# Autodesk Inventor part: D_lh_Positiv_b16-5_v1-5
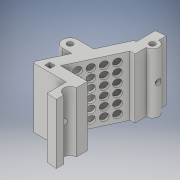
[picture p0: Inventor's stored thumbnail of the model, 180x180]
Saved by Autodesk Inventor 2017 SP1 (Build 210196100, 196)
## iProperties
Part Number: D_lh_Positiv_b16-5_v1-5
Material: Generisch
Document SubType Name: Modeling
Designer: haesner
Density: 1 g/cm^3
Appearance: Vorgabe
Part Number: D_lh_Positiv_b16-5_v1-6_3D-Druck
Author: haesner
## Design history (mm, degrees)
sketch "Skizze1"
  geometry: L1 (0, 9.5)-(-2, 9.5); L2 (-2, 9.5)-(-10.86, -9.5); L3 (-10.86, -9.5)-(0, -9.5); L4 (0, 22)-(0, 19); L5 (0, 14)-(0, 9.5); L6 (0, -22)-(0, -19); L7 (0, -9.5)-(0, -14); L8 (-26.9, 0)-(7.4, 0) reference; L9 (0, -30.8)-(0, 30.8) reference; C1 r 1.15 at (-16.5, 0); C2 r 1.15 at (0, 16.5); A1 r 22 centre (0, 0) between (0, 22) and (0, -22); A2 r 2.5 centre (0, 16.5) between (0, 14) and (0, 19); A3 r 2.5 centre (0, -16.5) between (0, -14) and (0, -19); 1 further point
  constraints: 14 end point, 6 point on circle, 5 centre point, 4 collinear, 4 point on line, 2 coincident, 2 equal radius, 1 horizontal, 1 parallel, 1 other
  dimensions: "d1" = 22 radius of A1; "d4" = 2.3 diameter of C2; "d5" = 2.5 radius of A3; "d6" = 16.5 distance from line of L8 A3.centre; "d7" = 16.5 distance from line of L8 A2.centre (= d6); "d8" = 16.5 distance from line of L9 C1.centre (= d6); "d10" = 19 distance between parallel lines of L3 L1; "d172" = 2 distance of L1.start L1.end; "d173" = 25 deg angle of L9 L2
extrude "Extrusion1" new body sketch "Skizze1" distance "d11" = 3; taper "d12" = 0 deg
sketch "Skizze12"
  geometry: L1 (0, 19)-(0, 22); L2 (0, -14)-(0, -9.5) reference; L3 (0, -9.5)-(-10.86, -9.5) reference; L4 (-10.86, -9.5)-(-2, 9.5) reference; L5 (-2, 9.5)-(0, 9.5) reference; L6 (0, 9.5)-(0, 14) reference; L7 (-4.867, 14)-(-17.569, -13.241); L8 (0, -22)-(0, -19) reference; L9 (-16.971, -14)-(-4, -14); L10 (-4, -14)-(-4, -21.633); L11 (-16.5, -3)-(-12.794, -3); L12 (-16.5, 3)-(-9.996, 3); L13 (-26.9, 0)-(7.4, 0) reference; L14 (-4, 21.633)-(-4, 14); L15 (-4.867, 14)-(-4, 14); C1 r 1.15 at (0, 16.5); C2 r 1.15 at (0, 16.5); C3 r 1.15 at (-16.5, 0) reference; A1 r 2.5 centre (0, 16.5) between (0, 14) and (0, 19); A2 r 22 centre (0, 0) between (-4, -21.633) and (0, -22); A3 r 2.5 centre (0, -16.5) between (0, -14) and (0, -19) reference; A4 r 22 centre (0, 0) between (0, 22) and (0, -22) reference; A5 r 3 centre (-16.5, 0) between (-16.5, 3) and (-16.5, -3); A6 r 22 centre (0, 0) between (0, 22) and (-4, 21.633); A7 r 22 centre (0, 0) between (-17.569, -13.241) and (-16.971, -14); 2 further points
  constraints: 16 end point, 11 point on circle, 7 centre point, 5 coincident, 4 horizontal, 2 point on line, 2 vertical, 1 parallel, 1 other
  dimensions: "d143" = 4.5 distance between parallel lines of L4 L7 (derived); "d145" = 4 distance between parallel lines of L8 L10 (derived); "d168" = 3 radius of A5; "d169" = 6 distance between parallel lines of L11 L12; "d174" = 4 distance between parallel lines of L1 L14 (derived); "d175" = 4.5 distance between parallel lines of L15 L5 (derived); "d176" = 4.5 distance between parallel lines of L3 L9 (derived)
extrude "Extrusion11" join sketch "Skizze12" distance "d109" = 18; taper "d110" = 0 deg
sketch "Skizze14"
  geometry: L1 (0, -22)-(0, -19); L2 (0, -14)-(0, -9.5); L3 (0, -9.5)-(-10.86, -9.5); L4 (-10.86, -9.5)-(-2, 9.5); L5 (-2, 9.5)-(0, 9.5); L6 (0, 9.5)-(0, 14); L7 (0, 19)-(0, 22); C1 r 1.15 at (0, 16.5); C2 r 1.15 at (-16.5, 0); A1 r 22 centre (0, 0) between (-4, -21.633) and (0, -22); A2 r 2.5 centre (0, -16.5) between (0, -14) and (0, -19); A3 r 2.5 centre (0, 16.5) between (0, 14) and (0, 19); A4 r 22 centre (0, 0) between (-4, 21.633) and (-17.569, -13.241) reference; A5 r 22 centre (0, 0) between (0, 22) and (-4, 21.633) reference; A6 r 22 centre (0, 0) between (-17.569, -13.241) and (-16.971, -14) reference; A7 r 22 centre (0, 0) between (-16.971, -14) and (-4, -21.633) reference; 1 further point
  constraints: 14 end point, 6 point on circle, 5 centre point
extrude "Extrusion14" join sketch "Skizze14" distance "d151" = 3; taper "d152" = 0 deg
sketch "Skizze7"
  geometry: L1 (6.6, -3.765)-(6.6, -7.765); L2 (6.6, -7.765)-(10.2, -7.765); L3 (10.2, -7.765)-(10.2, -3.765); L4 (10.2, -3.765)-(13.8, -3.765); L5 (13.8, -3.765)-(13.8, -7.765); L6 (13.8, -7.765)-(17.4, -7.765); L7 (17.4, -7.765)-(17.4, -3.765); L8 (17.4, -3.765)-(21, -3.765); L9 (21, -3.765)-(21, -7.765); L10 (21, -7.765)-(21, -11.765); L11 (21, -11.765)-(21, -15.765); L12 (21, -15.765)-(17.4, -15.765); L13 (17.4, -15.765)-(17.4, -11.765); L14 (17.4, -11.765)-(13.8, -11.765); L15 (13.8, -11.765)-(13.8, -15.765); L16 (10.2, -15.765)-(10.2, -11.765); L17 (6.6, -11.765)-(6.6, -15.765); L18 (10.2, -15.765)-(13.8, -15.765); L19 (10.2, -11.765)-(6.6, -11.765); L20 (6.6, -3.765)-(3, -3.765); L21 (3, -3.765)-(3, -7.765); L22 (6.6, -15.765)-(3, -15.765); L23 (3, -15.765)-(3, -11.765); L24 (24, -47.047)-(24, 23.277) reference; L25 (28.8, -7.765)-(-4.8, -7.765) reference
  constraints: 46 end point, 20 point on line, 10 equal length, 10 perpendicular, 3 horizontal, 2 vertical, 1 collinear
  dimensions: "d49" = 4 distance between parallel lines of L6 L14; "d50" = 4 distance of L17.start L17.end; "d59" = 3.6 distance of L7.end L8.end; "d177" = 3 distance between parallel lines of L24 L9
hole "Bohrung1" sketch "Skizze7" diameter "d52" = 3; stored, may be unused: countersink angle "d56" = 90 deg, drill point angle "d58" = 118 deg; dims "d53" = 6, "d54" = 4, "d55" = 2, "d57" = 1.8
sketch "Skizze8"
  geometry: L1 (7.86, -17.4)-(3.86, -17.4); L2 (3.86, -17.4)-(3.86, -13.8); L3 (3.86, -13.8)-(7.86, -13.8); L4 (7.86, -13.8)-(7.86, -10.2); L5 (7.86, -10.2)-(3.86, -10.2); L6 (3.86, -10.2)-(3.86, -6.6); L7 (3.86, -6.6)-(7.86, -6.6); L8 (7.86, -6.6)-(7.86, -3); L9 (7.86, -3)-(3.86, -3); L10 (7.86, -17.4)-(7.86, -21); L11 (7.86, -21)-(3.86, -21); L12 (-16.04, 0)-(18.26, 0) reference; L13 (10.86, 4.8)-(10.86, -28.8) reference; 3 further points; 1 other entity
  constraints: 22 end point, 9 equal length, 4 perpendicular, 3 parallel, 2 horizontal, 2 vertical, 3 other
  dimensions: "d60" = 4 distance of L1.start L1.end; "d61" = 3.6 distance of L1.end L2.end; "d139" = 2.5 dimension on L4; "d178" = 3 distance between parallel lines of L12 L9; "d179" = 3 distance between parallel lines of L13 L4
hole "Bohrung2" sketch "Skizze8" diameter "d64" = 3; stored, may be unused: countersink angle "d68" = 90 deg, drill point angle "d70" = 118 deg; dims "d65" = 6, "d66" = 4, "d67" = 2, "d69" = 1.8
sketch "Skizze6"
  geometry: L1 (10.86, -12.5)-(1, -12.5); L2 (14.17, -9.5)-(3.911, 12.5); L3 (3.911, 12.5)-(1, 12.5); L4 (1, -12.5)-(1, -10.5); L5 (0, -30.8)-(0, 30.8) reference; L6 (11.963, -9.5)-(2.637, 10.5); L7 (10.86, -10.5)-(1, -10.5); L8 (0, -9.5)-(10.86, -9.5) reference; L9 (2.637, 10.5)-(1, 10.5); L10 (1, 10.5)-(1, 12.5); L11 (2, 9.5)-(0, 9.5) reference; L12 (10.86, -9.5)-(2, 9.5) reference; L13 (10.86, -12.5)-(10.86, -10.5); L14 (11.963, -9.5)-(14.17, -9.5); 1 further point
  constraints: 20 end point, 5 horizontal, 2 point on line, 2 vertical, 1 perpendicular
  dimensions: "d41" = 1 distance between parallel lines of L5 L4; "d129" = 2 distance between parallel lines of L2 L6; "d130" = 1 distance between parallel lines of L8 L7; "d131" = 1 distance between parallel lines of L5 L10 (derived); "d132" = 2 distance between parallel lines of L3 L9; "d133" = 2 distance between parallel lines of L7 L1; "d134" = 1 distance between parallel lines of L11 L9 (derived); "d135" = 1 distance between parallel lines of L12 L6 (derived)
extrude "Extrusion6" cut sketch "Skizze6" distance "d39" = 23; taper "d40" = 0 deg
sketch "Skizze16"
  geometry: L1 (9, 38.133)-(9, 5.133); L2 (-7.8, 21.633)-(25.8, 21.633) reference; L3 (-3, -45.327)-(-3, 58.46) reference; 1 further point
  constraints: 2 end point, 1 symmetric about line, 1 vertical
  dimensions: "d160" = 33 distance of L1.start L1.end; "d180" = 12 distance between parallel lines of L3 L1
hole "Bohrung4" sketch "Skizze16" at (9, 38.133), (9, 5.133) diameter "d161" = 2.3; stored, may be unused: countersink angle "d165" = 90 deg, drill point angle "d167" = 118 deg; dims "d162" = 6, "d163" = 4, "d164" = 2, "d166" = 8
sketch "Skizze17"
  geometry: L1 (-4, 21.633)-(-4, 14) reference; L2 (-4, 14)-(-4.867, 14) reference; L3 (-4.867, 14)-(-9.996, 3) reference; L4 (-9.996, 3)-(-16.5, 3) reference; L5 (-16.5, -3)-(-12.794, -3) reference; L6 (-12.794, -3)-(-17.569, -13.241) reference; L7 (-16.971, -14)-(-4, -14) reference; L8 (-4, -14)-(-4, -21.633) reference; A1 r 22 centre (0, 0) between (0, 22) and (0, -22) reference; A2 r 3 centre (-16.5, 0) between (-16.5, 3) and (-16.5, -3) reference; 1 further point
extrude "Extrusion17" cut sketch "Skizze17" distance "d181" = 30; taper "d182" = 0 deg
sketch "Skizze18"
  geometry: L1 (11.963, -12.5)-(14.17, -12.5); L2 (14.17, -12.5)-(14.17, -10.5); L3 (14.17, -10.5)-(11.963, -10.5); L4 (11.963, -10.5)-(11.963, -12.5); L5 (14.17, -9.5)-(11.963, -9.5) reference; L6 (10.86, -10.5)-(10.86, -12.5) reference; 1 further point
  constraints: 8 end point, 4 parallel, 2 point on line, 1 horizontal, 1 perpendicular
extrude "Extrusion18" cut sketch "Skizze18" distance "d183" = 40; taper "d184" = 0 deg
sketch "Skizze19"
  geometry: L1 (11.963, -12.5)-(11.963, -10.5) reference; L2 (10.86, -10.5)-(10.86, -12.5) reference; L3 (14.17, -9.5)-(11.963, -9.5) reference; L4 (11.963, -10.5)-(14.17, -10.5) reference; L5 (10.86, -10.5)-(11.963, -10.5); L6 (10.86, -12.5)-(11.963, -12.5); L7 (11.963, -10.5)-(11.963, -9.5); L8 (14.17, -10.5)-(14.17, -9.5); 1 further point
  constraints: 8 end point, 2 parallel, 1 horizontal, 1 perpendicular
extrude "Extrusion19" cut sketch "Skizze19" distance "d185" = 10; taper "d186" = 0 deg
sketch "Skizze15"
  geometry: L1 (4, 14)-(4, 21.633) reference; L2 (16.971, 14)-(4, 14) reference; L3 (4, -21.633)-(4, -14) reference; L4 (4, -14)-(16.971, -14) reference; L5 (16.5, 3)-(9.996, 3) reference; L6 (12.794, -3)-(16.5, -3) reference; A1 r 22 centre (0, 0) between (0, -22) and (0, 22) reference; A2 r 22 centre (0, 0) between (0, -22) and (0, 22) reference; A3 r 3 centre (16.5, 0) between (16.5, -3) and (16.5, 3) reference; 4 further points; 2 other entities
  constraints: 2 other
extrude "Extrusion16" cut sketch "Skizze15" distance "d170" = 30; taper "d171" = 0 deg
sketch "Skizze13"
  geometry: L1 (9, 38.133)-(9, 5.133); L2 (-7.2, 21.633)-(22.2, 21.633) reference; L3 (-3, -9.167)-(-3, 52.433) reference; 1 further point
  constraints: 2 end point, 1 symmetric about line, 1 vertical
  dimensions: "d114" = 12 distance between parallel lines of L3 L1; "d115" = 33 distance of L1.start L1.end
hole "Bohrung3" sketch "Skizze13" at (9, 38.133), (9, 5.133) diameter "d116" = 2.3; stored, may be unused: countersink angle "d120" = 90 deg, drill point angle "d122" = 118 deg; dims "d117" = 6, "d118" = 4, "d119" = 2, "d121" = 8
sketch "Skizze9"
  geometry: L1 (-4, -20.274)-(-14, -14.5); L2 (-14, -14.5)-(-4, -14.5); L3 (-6.459, 16.5)-(-12.737, 3.038); L4 (-12.737, 3.038)-(-19.081, 5.996); L5 (0, 16.5)-(-33.947, 16.5); L6 (-6.459, 16.5)-(-9.459, 16.5); L7 (-19.081, 5.996)-(-9.459, 16.5); L8 (-4, -14.5)-(-4, -20.274); L9 (-40.966, 0)-(8.169, 0) reference; L10 (0, 25.235)-(0, -27.858) reference; L11 (-1, -12.5)-(-15.569, -12.5) reference; C1 r 1.15 at (0, 16.5) reference; 6 further points; 1 other entity
  constraints: 16 end point, 2 point on line, 1 coincident, 1 horizontal, 1 perpendicular, 1 vertical, 1 other
  dimensions: "d71" = 7 distance of L3.end L4.end; "d72" = 3 distance of L6.end L3.start; "d78" = 30 deg angle of L2 L1; "d100" = 10 distance of L1.end L2.end; "d123" = 4 distance between parallel lines of L10 L8; "d124" = 2 distance between parallel lines of L2 L11; "d125" = 4 dimension on L3
extrude "Extrusion7" cut sketch "Skizze9" distance "d79" = 30; taper "d80" = 0 deg
fillet "Rundung8" dims "d127" = 1
node "Volumenkörper1"
other parameters: "d29" = 1, "d36" = 2, "d112" = 4, "d113" = 4, "d142" = 4.5
